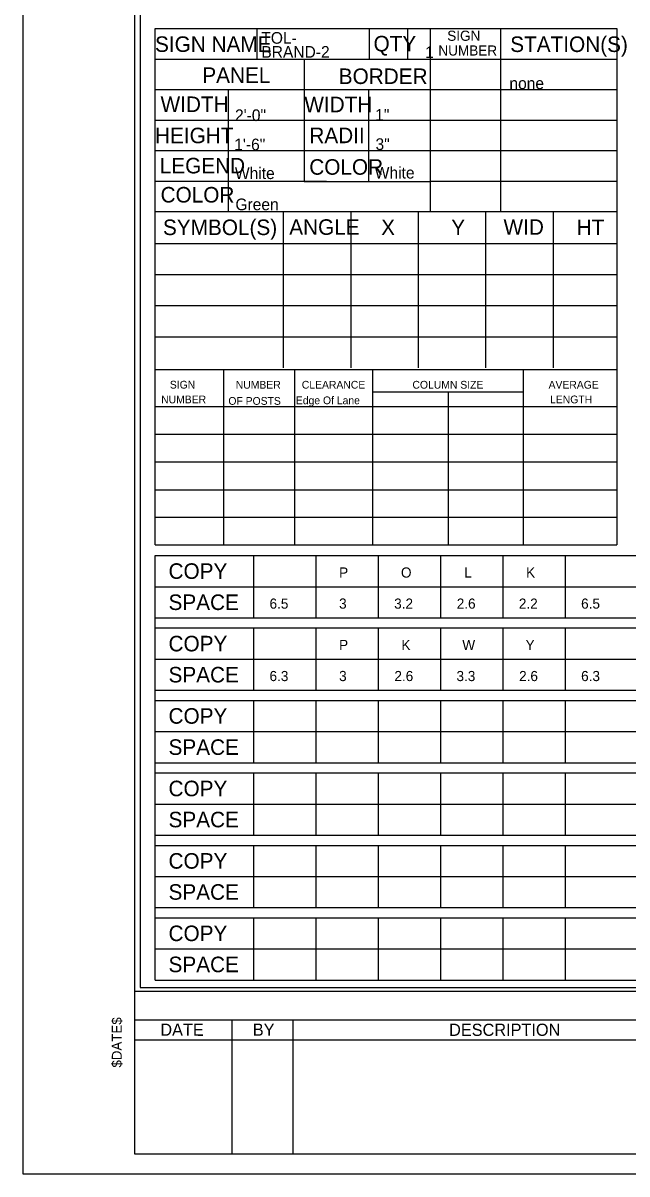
# Model space of a CAD drawing. Extents: x 17890628 to 17890754, y 17897693 to 17897992.
# Drawn here: x 17890687 to 17890694.3, y 17897874.81 to 17897888.7 of the extents above; entities that cross this region are included whole.
import ezdxf

# ---------------------------------------------------------------- set-up
doc = ezdxf.new("R2010")
doc.units = 0
for name, color, linetype in [('GSSign', 7, 'Continuous'), ('PlotBorder_dp', 7, 'Continuous'), ('SheetBorder_dp', 7, 'Continuous'), ('SheetLines_dp', 7, 'Continuous'), ('SheetLinesMisc2_dp', 7, 'Continuous'), ('TextMinor', 7, 'Continuous'), ('TextMisc', 7, 'Continuous')]:
    doc.layers.add(name, color=color, linetype=linetype)

msp = doc.modelspace()

# ---------------------------------------------------------------- linework, layer by layer
at = {"layer": 'PlotBorder_dp'}
msp.add_lwpolyline([(17890687.002, 17897874.814), (17890727.417, 17897874.814), (17890727.417, 17897900.777), (17890687.002, 17897900.777)], close=True, dxfattribs=at)
at = {"layer": 'SheetBorder_dp'}
for p, q in [((17890688.35, 17897900.533), (17890688.35, 17897875.059)), ((17890688.35, 17897877.018), (17890726.07, 17897877.018)), ((17890688.35, 17897875.059), (17890726.07, 17897875.059))]:
    msp.add_line(p, q, dxfattribs=at)
at = {"layer": 'SheetLines_dp'}
for p, q in [((17890688.35, 17897876.676), (17890702.458, 17897876.676)), ((17890689.525, 17897876.676), (17890689.525, 17897875.059)), ((17890690.26, 17897876.676), (17890690.26, 17897875.059)), ((17890688.35, 17897876.431), (17890702.458, 17897876.431))]:
    msp.add_line(p, q, dxfattribs=at)
at = {"layer": 'SheetLinesMisc2_dp'}
for p, q in [((17890688.417, 17897900.475), (17890688.417, 17897877.063)), ((17890688.597, 17897882.404), (17890688.597, 17897888.634)), ((17890688.597, 17897888.634), (17890694.174, 17897888.634)), ((17890689.827, 17897888.634), (17890689.827, 17897888.266)), ((17890691.182, 17897888.634), (17890691.182, 17897888.266)), ((17890691.645, 17897888.634), (17890691.645, 17897888.266)), ((17890691.921, 17897888.634), (17890691.921, 17897886.426)), ((17890692.77, 17897888.634), (17890692.77, 17897886.426)), ((17890694.174, 17897888.634), (17890694.174, 17897882.404)), ((17890688.597, 17897888.266), (17890694.174, 17897888.266)), ((17890690.4, 17897888.266), (17890690.4, 17897886.79)), ((17890688.597, 17897887.898), (17890694.174, 17897887.898)), ((17890689.479, 17897887.898), (17890689.479, 17897886.426)), ((17890691.177, 17897887.894), (17890691.177, 17897886.79)), ((17890688.597, 17897887.53), (17890694.174, 17897887.53)), ((17890688.597, 17897887.162), (17890694.174, 17897887.162)), ((17890688.597, 17897886.794), (17890690.666, 17897886.794)), ((17890690.4, 17897886.79), (17890691.921, 17897886.79)), ((17890691.921, 17897886.794), (17890694.174, 17897886.794)), ((17890688.597, 17897886.426), (17890694.174, 17897886.426)), ((17890690.146, 17897886.419), (17890690.146, 17897884.54)), ((17890690.961, 17897886.419), (17890690.961, 17897884.54)), ((17890691.776, 17897886.419), (17890691.776, 17897884.54)), ((17890692.59, 17897886.419), (17890692.59, 17897884.54)), ((17890693.405, 17897886.419), (17890693.405, 17897884.54)), ((17890688.599, 17897886.043), (17890694.174, 17897886.043)), ((17890688.599, 17897885.667), (17890694.174, 17897885.667)), ((17890688.599, 17897885.292), (17890694.174, 17897885.292)), ((17890688.599, 17897884.916), (17890694.174, 17897884.916)), ((17890688.597, 17897884.522), (17890694.174, 17897884.522)), ((17890689.425, 17897884.522), (17890689.425, 17897882.404)), ((17890690.28, 17897884.522), (17890690.28, 17897882.404)), ((17890691.225, 17897884.522), (17890691.225, 17897882.404)), ((17890693.043, 17897884.522), (17890693.043, 17897882.404)), ((17890691.225, 17897884.253), (17890693.042, 17897884.253)), ((17890692.138, 17897884.253), (17890692.138, 17897882.404)), ((17890688.597, 17897884.073), (17890694.174, 17897884.073)), ((17890688.597, 17897883.739), (17890694.174, 17897883.739)), ((17890688.597, 17897883.405), (17890694.174, 17897883.405)), ((17890688.597, 17897883.071), (17890694.174, 17897883.071)), ((17890688.597, 17897882.738), (17890694.174, 17897882.738)), ((17890688.597, 17897882.404), (17890694.174, 17897882.404)), ((17890688.597, 17897882.276), (17890707.094, 17897882.276)), ((17890688.597, 17897877.154), (17890688.597, 17897882.276)), ((17890689.788, 17897882.276), (17890689.788, 17897881.524)), ((17890690.541, 17897882.276), (17890690.541, 17897881.524)), ((17890691.293, 17897882.276), (17890691.293, 17897881.524)), ((17890692.045, 17897882.276), (17890692.045, 17897881.524)), ((17890692.798, 17897882.276), (17890692.798, 17897881.524)), ((17890693.55, 17897882.276), (17890693.55, 17897881.524)), ((17890688.597, 17897881.9), (17890707.094, 17897881.9)), ((17890688.597, 17897881.524), (17890707.094, 17897881.524)), ((17890688.597, 17897881.402), (17890707.094, 17897881.402)), ((17890689.788, 17897881.402), (17890689.788, 17897880.65)), ((17890690.541, 17897881.402), (17890690.541, 17897880.65)), ((17890691.293, 17897881.402), (17890691.293, 17897880.65)), ((17890692.045, 17897881.402), (17890692.045, 17897880.65)), ((17890692.798, 17897881.402), (17890692.798, 17897880.65)), ((17890693.55, 17897881.402), (17890693.55, 17897880.65)), ((17890688.597, 17897881.026), (17890707.094, 17897881.026)), ((17890688.597, 17897880.65), (17890707.094, 17897880.65)), ((17890688.597, 17897880.527), (17890707.094, 17897880.527)), ((17890689.788, 17897880.527), (17890689.788, 17897879.776)), ((17890690.541, 17897880.527), (17890690.541, 17897879.776)), ((17890691.293, 17897880.527), (17890691.293, 17897879.776)), ((17890692.045, 17897880.527), (17890692.045, 17897879.776)), ((17890692.798, 17897880.527), (17890692.798, 17897879.776)), ((17890693.55, 17897880.527), (17890693.55, 17897879.776)), ((17890688.597, 17897880.152), (17890707.094, 17897880.152)), ((17890688.597, 17897879.776), (17890707.094, 17897879.776)), ((17890688.597, 17897879.654), (17890707.094, 17897879.654)), ((17890689.788, 17897879.654), (17890689.788, 17897878.902)), ((17890690.541, 17897879.654), (17890690.541, 17897878.902)), ((17890691.293, 17897879.654), (17890691.293, 17897878.902)), ((17890692.045, 17897879.654), (17890692.045, 17897878.902)), ((17890692.798, 17897879.654), (17890692.798, 17897878.902)), ((17890693.55, 17897879.654), (17890693.55, 17897878.902)), ((17890688.597, 17897879.278), (17890707.094, 17897879.278)), ((17890688.597, 17897878.902), (17890707.094, 17897878.902)), ((17890688.597, 17897878.779), (17890707.094, 17897878.779)), ((17890689.788, 17897878.779), (17890689.788, 17897878.028)), ((17890690.541, 17897878.779), (17890690.541, 17897878.028)), ((17890691.293, 17897878.779), (17890691.293, 17897878.028)), ((17890692.045, 17897878.779), (17890692.045, 17897878.028)), ((17890692.798, 17897878.779), (17890692.798, 17897878.028)), ((17890693.55, 17897878.779), (17890693.55, 17897878.028)), ((17890688.597, 17897878.404), (17890707.094, 17897878.404)), ((17890688.597, 17897878.028), (17890707.094, 17897878.028)), ((17890688.597, 17897877.905), (17890707.094, 17897877.905)), ((17890689.788, 17897877.905), (17890689.788, 17897877.154)), ((17890690.541, 17897877.905), (17890690.541, 17897877.154)), ((17890691.293, 17897877.905), (17890691.293, 17897877.154)), ((17890692.045, 17897877.905), (17890692.045, 17897877.154)), ((17890692.798, 17897877.905), (17890692.798, 17897877.154)), ((17890693.55, 17897877.905), (17890693.55, 17897877.154)), ((17890688.597, 17897877.53), (17890707.094, 17897877.53)), ((17890688.597, 17897877.154), (17890707.094, 17897877.154)), ((17890688.417, 17897877.063), (17890726.026, 17897877.063))]:
    msp.add_line(p, q, dxfattribs=at)

# ---------------------------------------------------------------- texts
at = {"layer": 'GSSign'}
for s, height, p in [('TOL-', 0.1405, (17890689.881, 17897888.452)), ('BRAND-2', 0.1405, (17890689.881, 17897888.283)), ('1', 0.141, (17890691.859, 17897888.279)), ('none', 0.1406, (17890692.877, 17897887.904)), ('2\'-0"', 0.1406, (17890689.563, 17897887.519)), ('1"', 0.1406, (17890691.256, 17897887.524)), ('1\'-6"', 0.1406, (17890689.554, 17897887.166)), ('3"', 0.1406, (17890691.26, 17897887.17)), ('White', 0.1406, (17890689.562, 17897886.819)), ('White', 0.1406, (17890691.251, 17897886.825)), ('Green', 0.1406, (17890689.568, 17897886.443)), ('P', 0.123, (17890690.82, 17897882.01)), ('O', 0.123, (17890691.567, 17897882.01)), ('L', 0.123, (17890692.331, 17897882.01)), ('K', 0.123, (17890693.078, 17897882.01)), ('6.5', 0.1225, (17890689.98, 17897881.635)), ('3', 0.123, (17890690.82, 17897881.635)), ('3.2', 0.1225, (17890691.485, 17897881.635)), ('2.6', 0.1225, (17890692.241, 17897881.635)), ('2.2', 0.1225, (17890692.991, 17897881.635)), ('6.5', 0.1225, (17890693.743, 17897881.635)), ('P', 0.123, (17890690.82, 17897881.136)), ('K', 0.123, (17890691.573, 17897881.136)), ('W', 0.123, (17890692.308, 17897881.136)), ('Y', 0.123, (17890693.072, 17897881.136)), ('6.3', 0.1225, (17890689.98, 17897880.761)), ('3', 0.123, (17890690.82, 17897880.761)), ('2.6', 0.1225, (17890691.488, 17897880.761)), ('3.3', 0.1225, (17890692.238, 17897880.761)), ('2.6', 0.1225, (17890692.994, 17897880.761)), ('6.3', 0.1225, (17890693.743, 17897880.761))]:
    msp.add_text(s, height=height, dxfattribs=at).set_placement(p)
at = {"layer": 'TextMinor'}
for s, height, p in [('SIGN NAME', 0.1875, (17890688.597, 17897888.353)), ('QTY', 0.1875, (17890691.236, 17897888.359)), ('SIGN', 0.1225, (17890692.126, 17897888.487)), ('STATION(S)', 0.1875, (17890692.887, 17897888.352)), ('NUMBER', 0.1225, (17890692.019, 17897888.309)), ('PANEL', 0.1875, (17890689.168, 17897887.979)), ('BORDER', 0.1875, (17890690.816, 17897887.966)), ('WIDTH', 0.1875, (17890688.664, 17897887.628)), ('WIDTH', 0.1875, (17890690.4, 17897887.625)), ('HEIGHT', 0.1875, (17890688.597, 17897887.251)), ('RADII', 0.1875, (17890690.461, 17897887.252)), ('LEGEND', 0.1875, (17890688.654, 17897886.887)), ('COLOR', 0.1875, (17890690.46, 17897886.871)), ('COLOR', 0.1875, (17890688.664, 17897886.536)), ('SYMBOL(S)', 0.1875, (17890688.693, 17897886.143)), ('ANGLE', 0.1875, (17890690.218, 17897886.146)), ('X', 0.187, (17890691.328, 17897886.143)), ('Y', 0.187, (17890692.175, 17897886.143)), ('WID', 0.1875, (17890692.806, 17897886.146)), ('HT', 0.1875, (17890693.689, 17897886.143)), ('SIGN', 0.0937, (17890688.776, 17897884.291)), ('NUMBER', 0.0937, (17890689.572, 17897884.29)), ('CLEARANCE', 0.0937, (17890690.37, 17897884.29)), ('COLUMN SIZE', 0.09374, (17890691.706, 17897884.29)), ('AVERAGE', 0.0937, (17890693.35, 17897884.29)), ('NUMBER', 0.0937, (17890688.671, 17897884.113)), ('OF POSTS', 0.0937, (17890689.483, 17897884.095)), ('Edge Of Lane', 0.09374, (17890690.298, 17897884.102)), ('LENGTH', 0.0937, (17890693.368, 17897884.113)), ('COPY', 0.1875, (17890688.76, 17897881.995)), ('SPACE', 0.1875, (17890688.76, 17897881.619)), ('COPY', 0.1875, (17890688.76, 17897881.12)), ('SPACE', 0.1875, (17890688.76, 17897880.745)), ('COPY', 0.1875, (17890688.76, 17897880.247)), ('SPACE', 0.1875, (17890688.76, 17897879.871)), ('COPY', 0.1875, (17890688.76, 17897879.372)), ('SPACE', 0.1875, (17890688.76, 17897878.997)), ('COPY', 0.1875, (17890688.76, 17897878.498)), ('SPACE', 0.1875, (17890688.76, 17897878.123)), ('COPY', 0.1875, (17890688.76, 17897877.624)), ('SPACE', 0.1875, (17890688.76, 17897877.249))]:
    msp.add_text(s, height=height, dxfattribs=at).set_placement(p)
msp.add_text('$DATE$', height=0.12, rotation=90, dxfattribs=at).set_placement((17890688.195, 17897876.098))
at = {"layer": 'TextMisc'}
for s, height, rotation, p in [('DATE', 0.147, 359.8693, (17890688.661, 17897876.482)), ('DESCRIPTION', 0.14693, 0.0498, (17890692.149, 17897876.48))]:
    msp.add_text(s, height=height, rotation=rotation, dxfattribs=at).set_placement(p)
msp.add_text('BY', height=0.147, dxfattribs=at).set_placement((17890689.778, 17897876.482))

doc.saveas('drawing.dxf')
